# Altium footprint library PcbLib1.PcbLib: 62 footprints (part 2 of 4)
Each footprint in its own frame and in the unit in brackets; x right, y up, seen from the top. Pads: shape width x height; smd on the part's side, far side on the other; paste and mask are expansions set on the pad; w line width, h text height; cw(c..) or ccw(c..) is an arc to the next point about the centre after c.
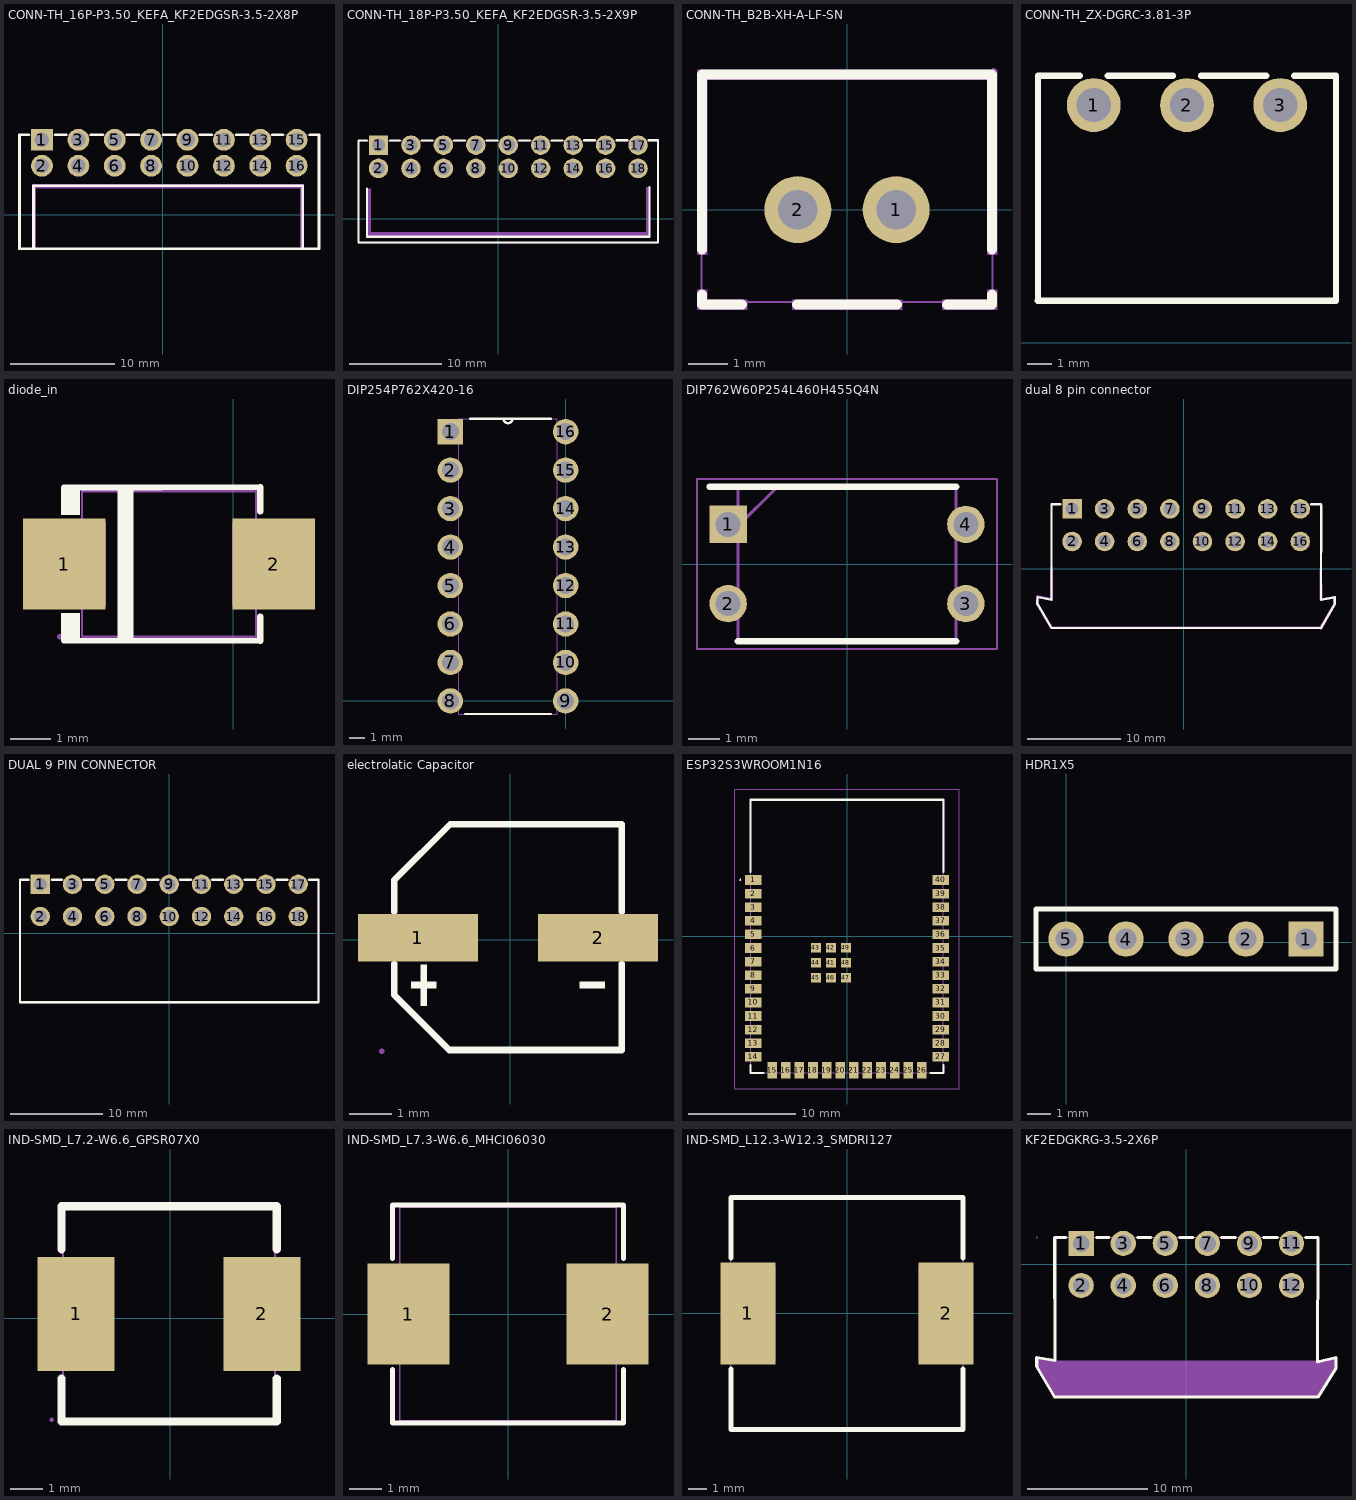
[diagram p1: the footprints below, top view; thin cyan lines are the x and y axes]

## CONN-TH_16P-P3.50_KEFA_KF2EDGSR-3.5-2X8P [mm]
pads (16):
  rect 2.1x2.1 hole 1.4 paste-2539.97 mask+0.05: 1(-11.633,7.219)
  round 2.1 hole 1.4 paste-2539.97 mask+0.05: 2(-11.633,4.719) 3(-8.133,7.219) 5(-4.633,7.219) 6(-4.633,4.719) 7(-1.133,7.219) 8(-1.133,4.719) 9(2.367,7.219) 10(2.367,4.719) 11(5.867,7.219) 12(5.867,4.719) 13(9.367,7.219) 14(9.367,4.719) 15(12.867,7.219) 16(12.867,4.719)
  round 2.1 hole 1.4 copper offset 0,0 paste-2539.97 mask+0.05: 4(-8.133,4.719)
Top Overlay:
  lines w0.254: -13.792,-3.281 -13.792,7.719 -12.914,7.719 ; -13.783,-3.281 15.017,-3.281 15.017,7.719 14.139,7.719 ; -12.448,-3.281 -12.448,2.794 13.444,2.794 13.444,-3.281 ; -10.352,7.719 -9.312,7.719 ; -6.954,7.719 -5.812,7.719 ; -3.454,7.719 -2.312,7.719 ; 0.046,7.719 1.188,7.719 ; 3.546,7.719 4.688,7.719 ; 7.046,7.719 8.188,7.719 ; 10.546,7.719 11.527,7.719
Mechanical 6:
  region: -12.591,-3.302 -12.591,2.921 13.571,2.921 13.571,-3.302 13.19,-3.302 13.19,2.54 -12.21,2.54 -12.21,-3.302
Mechanical 15:
  region: 8.967,5.119 9.767,5.119 9.767,4.319 8.967,4.319
  region: 8.967,7.619 9.767,7.619 9.767,6.819 8.967,6.819
  region: 5.467,5.119 6.267,5.119 6.267,4.319 5.467,4.319
  region: 5.467,7.619 6.267,7.619 6.267,6.819 5.467,6.819
  region: 1.967,5.119 2.767,5.119 2.767,4.319 1.967,4.319
  region: 1.967,7.619 2.767,7.619 2.767,6.819 1.967,6.819
  region: -1.533,5.119 -0.733,5.119 -0.733,4.319 -1.533,4.319
  region: -1.533,7.619 -0.733,7.619 -0.733,6.819 -1.533,6.819
  region: -5.033,5.119 -4.233,5.119 -4.233,4.319 -5.033,4.319
  region: -5.033,7.619 -4.233,7.619 -4.233,6.819 -5.033,6.819
  region: -12.033,7.619 -11.233,7.619 -11.233,6.819 -12.033,6.819
  region: -12.033,5.119 -11.233,5.119 -11.233,4.319 -12.033,4.319
  region: -8.533,7.619 -7.733,7.619 -7.733,6.819 -8.533,6.819
  region: -8.533,5.119 -7.733,5.119 -7.733,4.319 -8.533,4.319
  region: 12.467,5.119 13.267,5.119 13.267,4.319 12.467,4.319
  region: 12.467,7.619 13.267,7.619 13.267,6.819 12.467,6.819
  region: -13.723,7.719 -13.723,7.694 -13.758,7.659 -13.808,7.659 -13.843,7.694 -13.843,7.719 -13.843,7.744 -13.808,7.779 -13.758,7.779 -13.723,7.744
  lines w0.051: -13.783,-3.281 15.017,-3.281 15.017,7.719 -13.783,7.719 -13.783,-3.281

## CONN-TH_18P-P3.50_KEFA_KF2EDGSR-3.5-2X9P [mm]
pads (18):
  rect 2.1x2.1 hole 1.4 paste-2539.97 mask+0.05: 1(-12.903,7.96)
  round 2.1 hole 1.4 paste-2539.97 mask+0.05: 2(-12.903,5.46) 3(-9.403,7.96) 5(-5.903,7.96) 6(-5.903,5.46) 7(-2.403,7.96) 8(-2.403,5.46) 9(1.097,7.96) 10(1.097,5.46) 11(4.597,7.96) 12(4.597,5.46) 13(8.097,7.96) 14(8.097,5.46) 15(11.597,7.96) 17(15.097,7.96) 18(15.097,5.46)
  round 2.1 hole 1.4 copper offset 0,0 paste-2539.97 mask+0.05: 4(-9.403,5.46) 16(11.597,5.46)
Top Overlay:
  lines w0.254: -15.062,-2.54 -15.062,8.46 -14.184,8.46 ; -15.053,-2.54 17.247,-2.54 17.247,8.488 16.264,8.488 ; -14.143,3.281 -14.143,-1.926 16.337,-1.926 16.337,3.408 ; -11.622,8.46 -10.582,8.46 ; -8.224,8.46 -7.082,8.46 ; -4.724,8.46 -3.582,8.46 ; -1.224,8.46 -0.082,8.46 ; 2.276,8.46 3.418,8.46 ; 5.776,8.46 6.918,8.46 ; 9.264,8.488 10.43,8.488 ; 12.764,8.488 13.93,8.488
Mechanical 6:
  region: 16.337,3.408 16.337,-1.799 -14.143,-1.799 -14.143,3.281 -13.762,3.281 -13.762,-1.418 15.956,-1.418 15.956,3.408
Mechanical 15:
  region: 7.697,5.86 8.497,5.86 8.497,5.06 7.697,5.06
  region: 7.697,8.36 8.497,8.36 8.497,7.56 7.697,7.56
  region: 4.197,5.86 4.997,5.86 4.997,5.06 4.197,5.06
  region: 4.197,8.36 4.997,8.36 4.997,7.56 4.197,7.56
  region: 0.697,5.86 1.497,5.86 1.497,5.06 0.697,5.06
  region: 0.697,8.36 1.497,8.36 1.497,7.56 0.697,7.56
  region: -2.803,5.86 -2.003,5.86 -2.003,5.06 -2.803,5.06
  region: -2.803,8.36 -2.003,8.36 -2.003,7.56 -2.803,7.56
  region: -6.303,5.86 -5.503,5.86 -5.503,5.06 -6.303,5.06
  region: -6.303,8.36 -5.503,8.36 -5.503,7.56 -6.303,7.56
  region: -13.303,8.36 -12.503,8.36 -12.503,7.56 -13.303,7.56
  region: -13.303,5.86 -12.503,5.86 -12.503,5.06 -13.303,5.06
  region: -9.803,8.36 -9.003,8.36 -9.003,7.56 -9.803,7.56
  region: -9.803,5.86 -9.003,5.86 -9.003,5.06 -9.803,5.06
  region: 11.197,8.36 11.997,8.36 11.997,7.56 11.197,7.56
  region: 11.197,5.86 11.997,5.86 11.997,5.06 11.197,5.06
  region: 14.697,8.36 15.497,8.36 15.497,7.56 14.697,7.56
  region: 14.697,5.86 15.497,5.86 15.497,5.06 14.697,5.06
  region: -14.993,8.46 -14.993,8.435 -15.028,8.4 -15.078,8.4 -15.113,8.435 -15.113,8.46 -15.113,8.485 -15.078,8.52 -15.028,8.52 -14.993,8.485
  lines w0.051: -15.053,-2.54 17.247,-2.54 17.247,8.46 -15.053,8.46 -15.053,-2.54

## CONN-TH_B2B-XH-A-LF-SN [mm]
pads (2):
  round 1.7 hole 1: 1(1.25,0) 2(-1.25,0)
Top Overlay:
  lines w0.254: -3.683,-2.159 -3.683,-2.413 -2.667,-2.413 ; -3.683,-1.016 -3.683,3.429 3.683,3.429 3.683,-1.016 ; -1.27,-2.413 1.27,-2.413 ; 2.54,-2.413 3.683,-2.413 3.683,-2.159
Mechanical 6:
  region: -1.397,-2.54 -1.397,-2.286 1.397,-2.286 1.397,-2.54
  region: 2.413,-2.54 3.81,-2.54 3.81,-2.032 3.556,-2.032 3.556,-2.286 2.413,-2.286
  region: -2.54,-2.54 -3.81,-2.54 -3.81,-2.032 -3.556,-2.032 -3.556,-2.286 -2.54,-2.286
  region: -3.81,-1.143 -3.81,3.556 3.81,3.556 3.81,-1.143 3.556,-1.143 3.556,3.302 -3.556,3.302 -3.556,-1.143
Mechanical 15:
  region: 3.787,3.527 3.787,3.502 3.752,3.467 3.702,3.467 3.667,3.502 3.667,3.527 3.667,3.552 3.702,3.587 3.752,3.587 3.787,3.552
  region: -0.95,-0.32 -1.59,-0.32 -1.59,0.32 -0.95,0.32
  region: 1.59,-0.32 0.95,-0.32 0.95,0.32 1.59,0.32
  lines w0.051: -3.7,-2.35 -3.7,3.4 3.7,3.4 3.7,-2.35 -3.7,-2.35

## CONN-TH_ZX-DGRC-3.81-3P [mm]
pads (3):
  round 2.2 hole 1.4: 1(7.567,9.711) 2(11.377,9.711) 3(15.187,9.711)
Top Overlay:
  lines w0.254: 5.283,1.711 17.467,1.711 17.467,10.911 15.76,10.911 ; 5.287,1.711 5.287,10.911 6.994,10.911 ; 8.14,10.911 10.804,10.911 ; 11.95,10.911 14.614,10.911
Mechanical 15:
  region: 5.327,1.711 5.327,1.686 5.292,1.651 5.242,1.651 5.207,1.686 5.207,1.711 5.207,1.736 5.242,1.771 5.292,1.771 5.327,1.736

## diode_in [mm]
pads (2):
  rect 2.047x2.241 smd: 1(-4.183,4.445) 2(0.999,4.445)
Top Overlay:
  region: -2.862,6.337 -2.862,2.55 -2.481,2.55 -2.481,6.338
  region: -4.259,6.35 -4.259,5.66 -3.802,5.66 -3.802,6.35
  region: -4.259,2.54 -4.259,3.23 -3.802,3.23 -3.802,2.54
  lines w0.152: -4.189,6.334 0.661,6.35 0.665,6.35 0.665,5.746 ; -4.185,2.553 0.665,2.54 0.665,3.144
Mechanical 6:
  region: 0.179,4.316 0.179,4.57 1.83,4.57 1.83,4.316
  region: 1.132,3.617 0.878,3.617 0.878,5.268 1.132,5.268
  region: -5.084,4.318 -5.084,4.572 -3.433,4.572 -3.433,4.318
Mechanical 15:
  region: 1.108,3.408 -0.032,3.408 -0.032,5.483 1.108,5.483
  region: -4.292,5.482 -3.152,5.482 -3.152,3.408 -4.292,3.408
  region: -4.232,2.645 -4.232,2.62 -4.267,2.585 -4.317,2.585 -4.352,2.62 -4.352,2.645 -4.352,2.67 -4.317,2.705 -4.267,2.705 -4.232,2.67
  lines w0.051: -3.742,2.645 0.558,2.645 0.558,6.245 -3.742,6.245 -3.742,2.645

## DIP254P762X420-16 [mil]
pads (16):
  rect 66x66 hole 44: 1(-300,700)
  round 66 hole 44: 2(-300,600) 3(-300,500) 4(-300,400) 5(-300,300) 6(-300,200) 7(-300,100) 8(-300,0) 9(0,0) 10(0,100) 11(0,200) 12(0,300) 13(0,400) 14(0,500) 15(0,600) 16(0,700)
Top Overlay:
  lines w6: -261,-34 -39,-34 ; -248,734 -162,734 ; -39,734 -138,734 ; -162,734 ccw(c-150,734) -138,734 ; -162,734 -138,734
Mechanical 13:
  lines w0: -162,734 ccw(c-150,734) -138,734 ; -162,734 -138,734 ; -162,734 -278,734 -278,-34 -22,-34 -22,734 -138,734 ; -322,-22 -322,22 -278,22 -278,-22 -322,-22 ; -322,78 -322,122 -278,122 -278,78 -322,78 ; -322,178 -322,222 -278,222 -278,178 -322,178 ; -322,278 -322,322 -278,322 -278,278 -322,278 ; -322,378 -322,422 -278,422 -278,378 -322,378 ; -322,478 -322,522 -278,522 -278,478 -322,478 ; -322,578 -322,622 -278,622 -278,578 -322,578 ; -322,678 -322,722 -278,722 -278,678 -322,678 ; -22,-22 -22,22 22,22 22,-22 -22,-22 ; -22,78 -22,122 22,122 22,78 -22,78 ; -22,178 -22,222 22,222 22,178 -22,178 ; -22,278 -22,322 22,322 22,278 -22,278 ; -22,378 -22,422 22,422 22,378 -22,378 ; -22,478 -22,522 22,522 22,478 -22,478 ; -22,578 -22,622 22,622 22,578 -22,578 ; -22,678 -22,722 22,722 22,678 -22,678
3D body "PCF8574P,112.STEP": height 165.35, standoff -130.91, extent -335.69,-26.9 36.06,722.12

## DIP762W60P254L460H455Q4N [mm]
pads (4):
  rect 1.2x1.2 hole 0.8: 1(-3.81,1.27)
  round 1.2 hole 0.8: 2(-3.81,-1.27) 3(3.81,-1.27) 4(3.81,1.27)
Top Overlay:
  lines w0.2: -4.41,2.475 3.5,2.475 ; -3.5,-2.475 3.5,-2.475
Mechanical 13:
  lines w0.1: -3.5,1.205 -2.23,2.475 ; -3.5,-2.475 3.5,-2.475 3.5,2.475 -3.5,2.475 -3.5,-2.475
Mechanical 15:
  lines w0.05: -4.81,-2.725 4.81,-2.725 4.81,2.725 -4.81,2.725 -4.81,-2.725
3D body "PC817X4NSZ1B.stp": height 4.55, standoff -3.5, extent -3.96,-2.3 3.96,2.3

## dual 8 pin connector [mm]
pads (16):
  rect 2.1x2.1 hole 1.4 paste-2539.97 mask+0.05: 1(-11.968,6.421)
  round 2.1 hole 1.4 paste-2539.97 mask+0.05: 2(-11.968,2.921) 3(-8.468,6.421) 4(-8.468,2.921) 5(-4.968,6.421) 6(-4.968,2.921) 7(-1.468,6.421) 8(-1.468,2.921) 9(2.032,6.421) 10(2.032,2.921) 11(5.532,6.421) 12(5.532,2.921) 13(9.032,6.421) 14(9.032,2.921) 15(12.532,6.421) 16(12.532,2.921)
Top Overlay:
  lines w0.254: -14.171,6.915 -14.172,-3.332 -15.676,-3.038 -15.689,-3.78 -14.158,-6.367 14.755,-6.377 16.25,-3.743 16.241,-3.057 14.764,-3.339 14.77,6.824 ; -14.168,6.921 -13.249,6.921 ; 13.711,6.921 14.732,6.921
Mechanical 15:
  region: -14.042,0.03 -14.042,-3.254 -14.042,-3.282 -14.066,-3.333 -14.109,-3.369 -14.163,-3.384 -14.191,-3.379 -15.555,-3.149 -15.583,-3.784 -14.116,-6.211 14.646,-6.21 16.113,-3.71 16.086,-3.212 14.786,-3.424 14.758,-3.429 14.705,-3.414 14.662,-3.378 14.639,-3.328 14.638,-3.3 14.601,-0.046 14.6,0.007 14.674,0.082 14.779,0.083 14.854,0.01 14.855,-0.043 14.891,-3.15 16.184,-2.938 16.211,-2.934 16.263,-2.948 16.305,-2.982 16.33,-3.03 16.331,-3.057 16.369,-3.734 16.37,-3.743 16.368,-3.762 16.363,-3.78 16.357,-3.797 16.352,-3.805 14.828,-6.402 14.819,-6.416 14.796,-6.439 14.767,-6.456 14.735,-6.464 14.718,-6.464 -14.188,-6.465 -14.204,-6.465 -14.236,-6.457 -14.264,-6.441 -14.288,-6.418 -14.296,-6.404 -15.82,-3.882 -15.825,-3.874 -15.832,-3.857 -15.837,-3.839 -15.839,-3.82 -15.838,-3.811 -15.802,-2.994 -15.801,-2.967 -15.776,-2.918 -15.734,-2.884 -15.681,-2.87 -15.654,-2.875 -14.296,-3.104 -14.296,0.03 -14.296,0.083 -14.222,0.157 -14.117,0.157 -14.042,0.083

## DUAL 9 PIN CONNECTOR [mm]
pads (18):
  rect 2.1x2.1 hole 1.4 paste-2539.97 mask+0.05: 1(-14,5.334)
  round 2.1 hole 1.4 paste-2539.97 mask+0.05: 2(-14,1.834) 3(-10.5,5.334) 4(-10.5,1.834) 5(-7,5.334) 6(-7,1.834) 7(-3.5,5.334) 8(-3.5,1.834) 9(0,5.334) 10(0,1.834) 11(3.5,5.334) 12(3.5,1.834) 13(7,5.334) 14(7,1.834) 15(10.5,5.334) 16(10.5,1.834)
  round 2.1 hole 1.4 copper offset 0,0 paste-2539.97 mask+0.05: 17(14,5.334) 18(14,1.834)
Top Overlay:
  lines w0.254: -15.281,5.834 -16.2,5.834 -16.2,-7.466 16.2,-7.466 16.2,5.743 ; -12.719,5.834 -11.679,5.834 ; -9.321,5.834 -8.179,5.834 ; -5.821,5.834 -4.679,5.834 ; -2.321,5.834 -1.179,5.834 ; 1.179,5.834 2.321,5.834 ; 4.679,5.834 5.821,5.834 ; 8.179,5.834 9.321,5.834 ; 11.679,5.834 12.7,5.834 12.821,5.834 ; 15.179,5.834 16.2,5.834
Mechanical 6:
  region: 16.256,5.87 16.256,-7.465 16.129,-7.592 -16.129,-7.592 -16.256,-7.465 -16.256,5.87 -16.129,5.87 -16.129,-7.465 16.129,-7.465 16.129,5.87
Mechanical 15:
  region: 6.6,5.734 7.4,5.734 7.4,4.934 6.6,4.934
  region: 10.1,5.734 10.9,5.734 10.9,4.934 10.1,4.934
  region: -14.4,5.734 -13.6,5.734 -13.6,4.934 -14.4,4.934
  region: -14.4,2.234 -13.6,2.234 -13.6,1.434 -14.4,1.434
  region: -10.9,5.734 -10.1,5.734 -10.1,4.934 -10.9,4.934
  region: -10.9,2.234 -10.1,2.234 -10.1,1.434 -10.9,1.434
  region: -7.4,5.734 -6.6,5.734 -6.6,4.934 -7.4,4.934
  region: -7.4,2.234 -6.6,2.234 -6.6,1.434 -7.4,1.434
  region: -3.9,5.734 -3.1,5.734 -3.1,4.934 -3.9,4.934
  region: -3.9,2.234 -3.1,2.234 -3.1,1.434 -3.9,1.434
  region: -0.4,5.734 0.4,5.734 0.4,4.934 -0.4,4.934
  region: -0.4,2.234 0.4,2.234 0.4,1.434 -0.4,1.434
  region: 3.1,5.734 3.9,5.734 3.9,4.934 3.1,4.934
  region: 3.1,2.234 3.9,2.234 3.9,1.434 3.1,1.434
  region: 6.6,2.234 7.4,2.234 7.4,1.434 6.6,1.434
  region: 10.1,2.234 10.9,2.234 10.9,1.434 10.1,1.434
  region: 13.6,2.234 14.4,2.234 14.4,1.434 13.6,1.434
  region: 13.6,5.734 14.4,5.734 14.4,4.934 13.6,4.934
  region: -16.196,5.834 -16.196,5.859 -16.231,5.894 -16.281,5.894 -16.316,5.859 -16.316,5.834 -16.316,5.809 -16.281,5.774 -16.231,5.774 -16.196,5.809
  lines w0.051: -16.256,-7.465 -16.2,5.834 16.2,5.834 16.2,-7.466 -16.256,-7.465

## electrolatic Capacitor [mm]
pads (2):
  rect 2.8x1.1 smd: 1(-2.156,0.043) 2(2.044,0.043)
Top Overlay:
  region: -2.096,-0.581 -2.096,-1.541 -1.952,-1.541 -1.952,-0.581
  region: -2.312,-0.989 -2.312,-1.133 -1.736,-1.133 -1.736,-0.989
  region: 2.2,-0.989 2.2,-1.133 1.624,-1.133 1.624,-0.989
  lines w0.152: -2.715,-0.564 -2.715,-1.288 -1.428,-2.576 2.593,-2.576 2.593,-0.564 ; -2.715,0.65 -2.715,1.384 -1.405,2.692 2.603,2.692 2.603,0.65
Mechanical 6:
  region: -2.096,0.523 -2.096,-0.437 -1.952,-0.437 -1.952,0.523
  region: -2.312,0.115 -2.312,-0.029 -1.736,-0.029 -1.736,0.115
  region: 2.2,0.115 2.2,-0.029 1.624,-0.029 1.624,0.115
Mechanical 15:
  region: 2.894,-0.277 0.794,-0.277 0.794,0.373 2.894,0.373
  region: -3.006,0.373 -0.906,0.373 -0.906,-0.277 -3.006,-0.277
  region: -2.946,-2.607 -2.947,-2.583 -2.982,-2.549 -3.03,-2.549 -3.065,-2.583 -3.066,-2.607 -3.065,-2.631 -3.03,-2.665 -2.982,-2.665 -2.947,-2.631
  lines w0.051: -2.706,-1.307 -2.706,1.393 -1.406,2.693 2.594,2.693 2.594,-2.607 -1.406,-2.607 -2.706,-1.307
3D body "UCK1V172MNJ1MS.stp": height 22, standoff 0, extent -7.051,-6.842 6.949,6.958

## ESP32S3WROOM1N16 [mm]
pads (49):
  rect 1.5x0.9 smd: 1(-8.75,5.26) 2(-8.75,3.99) 3(-8.75,2.72) 4(-8.75,1.45) 5(-8.75,0.18) 6(-8.75,-1.09) 7(-8.75,-2.36) 8(-8.75,-3.63) 9(-8.75,-4.9) 10(-8.75,-6.17) 11(-8.75,-7.44) 12(-8.75,-8.71) 13(-8.75,-9.98) 14(-8.75,-11.25) 27(8.75,-11.25) 28(8.75,-9.98) 29(8.75,-8.71) 30(8.75,-7.44) 31(8.75,-6.17) 32(8.75,-4.9) 33(8.75,-3.63) 34(8.75,-2.36) 35(8.75,-1.09) 36(8.75,0.18) 37(8.75,1.45) 38(8.75,2.72) 39(8.75,3.99) 40(8.75,5.26)
  rect 0.9x1.5 smd: 15(-6.985,-12.5) 16(-5.715,-12.5) 17(-4.445,-12.5) 18(-3.175,-12.5) 19(-1.905,-12.5) 20(-0.635,-12.5) 21(0.635,-12.5) 22(1.905,-12.5) 23(3.175,-12.5) 24(4.445,-12.5) 25(5.715,-12.5) 26(6.985,-12.5)
  rect 0.9x0.9 smd: 41(-1.5,-2.46) 42(-1.5,-1.06) 43(-2.9,-1.06) 44(-2.9,-2.46) 45(-2.9,-3.86) 46(-1.5,-3.86) 47(-0.1,-3.86) 48(-0.1,-2.46) 49(-0.1,-1.06)
Top Overlay:
  lines w0.1: -10,5.26 ccw(c-9.95,5.26) -9.9,5.26 ccw(c-9.95,5.26) -10,5.26
  lines w0.2: -9,-12 -9,-12.75 -7.8,-12.75 ; -9,6 -9,12.75 9,12.75 9,6 ; 7.8,-12.75 9,-12.75 9,-12
Mechanical 13:
  lines w0.1: -9,-12.75 9,-12.75 9,12.75 -9,12.75 -9,-12.75
Mechanical 15:
  lines w0.1: -10.5,-14.25 10.5,-14.25 10.5,13.75 -10.5,13.75 -10.5,-14.25
3D body "ESP32-S3-WROOM-1-N16.stp": height 3.25, standoff 0, extent -9,-12.76 9,12.74

## HDR1X5 [mm] "Connector; Header; 5 Position"
pads (5):
  rect 1.5x1.5 hole 0.9: 1(10.16,0.127)
  round 1.5 hole 0.9: 2(7.62,0.127) 3(5.08,0.127) 4(2.54,0.127) 5(0,0.127)
Top Overlay:
  lines w0.2: -1.27,-1.143 -1.27,1.397 11.43,1.397 11.43,-1.143 -1.27,-1.143

## IND-SMD_L7.2-W6.6_GPSR07X0 [mm]
pads (2):
  rect 2.35x3.5 smd: 1(-2.889,0.135) 2(2.811,0.135)
Top Overlay:
  lines w0.254: -3.339,-1.846 -3.339,-3.165 3.261,-3.165 3.261,-1.846 ; -3.339,2.116 -3.339,3.435 3.261,3.435 3.261,2.116
Mechanical 15:
  region: -1.939,-1.365 -3.639,-1.365 -3.639,1.635 -1.939,1.635
  region: 1.861,1.635 3.561,1.635 3.561,-1.365 1.861,-1.365
  region: -3.579,-3.115 -3.579,-3.14 -3.614,-3.175 -3.664,-3.175 -3.699,-3.14 -3.699,-3.115 -3.699,-3.09 -3.664,-3.055 -3.614,-3.055 -3.579,-3.09
  lines w0.051: -3.289,-3.115 -3.289,3.385 3.211,3.385 3.211,-3.115 -3.289,-3.115

## IND-SMD_L7.3-W6.6_MHCI06030 [mm]
pads (2):
  rect 2.524x3.12 smd: 1(-3.078,0) 2(3.078,0)
Top Overlay:
  lines w0.152: -3.576,-1.712 -3.576,-3.376 3.576,-3.376 3.576,-1.712 ; -3.576,1.712 -3.576,3.376 3.576,3.376 3.576,1.712
Mechanical 15:
  region: -3.492,-3.307 -3.492,-3.332 -3.527,-3.367 -3.577,-3.367 -3.612,-3.332 -3.612,-3.307 -3.612,-3.282 -3.577,-3.247 -3.527,-3.247 -3.492,-3.282
  region: 1.951,1.45 3.551,1.45 3.551,-1.45 1.951,-1.45
  region: -1.948,-1.45 -3.548,-1.45 -3.548,1.45 -1.948,1.45
  lines w0.051: -3.35,-3.3 -3.35,3.3 3.35,3.3 3.35,-3.3 -3.35,-3.3

## IND-SMD_L12.3-W12.3_SMDRI127 [mm]
pads (2):
  rect 2.9x5.4 smd: 1(-5.25,0) 2(5.25,0)
Top Overlay:
  lines w0.254: -6.15,-2.931 -6.15,-6.15 6.15,-6.15 6.15,-2.931 ; -6.15,2.931 -6.15,6.15 6.15,6.15 6.15,2.931
Mechanical 15:
  region: 3.8,2.5 6.15,2.5 6.15,-2.5 3.8,-2.5
  region: -6.15,2.5 -3.8,2.5 -3.8,-2.5 -6.15,-2.5
  region: -6.09,-6.15 -6.09,-6.175 -6.125,-6.21 -6.175,-6.21 -6.21,-6.175 -6.21,-6.15 -6.21,-6.125 -6.175,-6.09 -6.125,-6.09 -6.09,-6.125
  lines w0.051: -6.15,-6.15 -6.15,6.15 6.15,6.15 6.15,-6.15 -6.15,-6.15

## KF2EDGKRG-3.5-2X6P [mm]
pads (12):
  rect 2.1x2.1 hole 1.4 paste-2539.97 mask+0.05: 1(-8.75,1.75)
  round 2.1 hole 1.4 paste-2539.97 mask+0.05: 2(-8.75,-1.75) 3(-5.25,1.75) 4(-5.25,-1.75) 5(-1.75,1.75) 6(-1.75,-1.75) 7(1.75,1.75) 8(1.75,-1.75) 9(5.25,1.75) 10(5.25,-1.75) 11(8.75,1.75) 12(8.75,-1.75)
Top Overlay:
  lines w0.254: -10.031,2.25 -10.95,2.25 -10.922,-8.001 -12.446,-7.747 -12.446,-8.509 -10.95,-11.05 10.95,-11.05 12.446,-8.636 12.446,-7.747 10.922,-8.128 10.95,2.25 9.929,2.25 ; -7.469,2.25 -6.429,2.25 ; -4.071,2.25 -2.929,2.25 ; -0.571,2.25 0.571,2.25 ; 2.929,2.25 4.071,2.25 ; 6.429,2.25 7.571,2.25
Mechanical 6:
  region: -10.922,-8.001 -12.446,-7.747 -12.446,-8.509 -10.922,-11.049 10.922,-11.049 12.446,-8.382 12.446,-7.747 10.922,-8.001 -10.16,-8.001
Mechanical 15:
  region: -12.39,2.256 -12.39,2.281 -12.425,2.316 -12.475,2.316 -12.51,2.281 -12.51,2.256 -12.51,2.231 -12.475,2.196 -12.425,2.196 -12.39,2.231
  region: -9.15,2.15 -8.35,2.15 -8.35,1.35 -9.15,1.35
  region: -9.15,-1.35 -8.35,-1.35 -8.35,-2.15 -9.15,-2.15
  region: -5.65,2.15 -4.85,2.15 -4.85,1.35 -5.65,1.35
  region: -5.65,-1.35 -4.85,-1.35 -4.85,-2.15 -5.65,-2.15
  region: -2.15,2.15 -1.35,2.15 -1.35,1.35 -2.15,1.35
  region: -2.15,-1.35 -1.35,-1.35 -1.35,-2.15 -2.15,-2.15
  region: 1.35,2.15 2.15,2.15 2.15,1.35 1.35,1.35
  region: 1.35,-1.35 2.15,-1.35 2.15,-2.15 1.35,-2.15
  region: 4.85,2.15 5.65,2.15 5.65,1.35 4.85,1.35
  region: 4.85,-1.35 5.65,-1.35 5.65,-2.15 4.85,-2.15
  region: 8.35,2.15 9.15,2.15 9.15,1.35 8.35,1.35
  region: 8.35,-1.35 9.15,-1.35 9.15,-2.15 8.35,-2.15
  lines w0.051: -12.45,-8.45 -10.954,-11.051 10.95,-11.05 12.45,-8.451 12.45,-7.75 10.949,-8.021 10.949,2.256 -10.954,2.256 -10.95,-8.02 -12.449,-7.75 -12.45,-8.45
